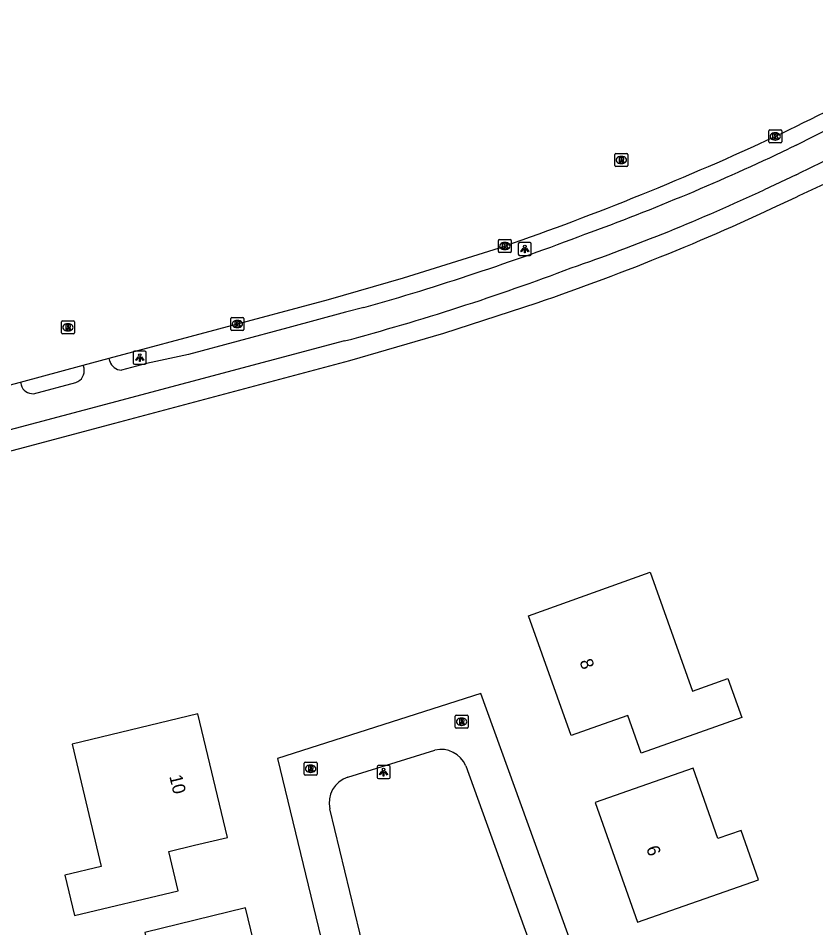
# Model space of a CAD drawing. Extents: x 162675 to 163482, y 379761 to 381227.
# Drawn here: x 162939.9 to 163001.5, y 380812.4 to 380882.6 of the extents above; entities that cross this region are included whole.
import ezdxf

# ---------------------------------------------------------------- set-up
doc = ezdxf.new("R2010")
doc.units = 0
for name, color, linetype in [('IMGEO_Fietspad_open', 7, 'Continuous'), ('IMGEO_Kolk', 7, 'Continuous'), ('IMGEO_Lichtpunt', 7, 'Continuous'), ('IMGEO_Pand', 7, 'Continuous'), ('IMGEO_Pand_nummerreeks', 7, 'Continuous'), ('IMGEO_Rijbaan_lokaal_gesloten', 7, 'Continuous'), ('IMGEO_Rioolput', 7, 'Continuous'), ('IMGEO_Voetpad_open', 7, 'Continuous')]:
    doc.layers.add(name, color=color, linetype=linetype)

msp = doc.modelspace()

# ---------------------------------------------------------------- linework, layer by layer
at = {"layer": 'IMGEO_Fietspad_open'}
for points in [[(163000.009, 380872.843), (162999.411, 380872.547)], [(163000, 380870.549), (162997.546, 380869.389)], [(162966.635, 380860.294), (162965.204, 380859.933), (162960.769, 380858.729), (162953.091, 380856.665), (162949.842, 380855.977), (162947.908, 380855.475)], [(162965.132, 380857.723), (162947.072, 380852.929), (162883.309, 380836.002), (162829.587, 380821.611), (162829.396, 380821.566)], [(162947.01, 380856.162), (162946.953, 380856.388)], [(162945.022, 380855.613), (162944.959, 380855.848)], [(162940.109, 380854.549), (162940.164, 380854.327)], [(162941.129, 380853.653), (162944.388, 380854.52)]]:
    msp.add_lwpolyline(points, dxfattribs=at)
for centre, radius, start, end in [((162863.234, 381148.559), 307.777, 296.38462, 299.42705), ((162902.998, 381072.888), 224.389, 295.61337, 299.67767), ((162922.893, 381032.807), 177.59, 290.02175, 295.5226), ((162931.903, 381010.136), 155.302, 289.07011, 295.00391), ((162907.827, 381066.245), 214.183, 285.93638, 290.74602), ((162917.882, 381034.623), 183.102, 284.95472, 290.71356), ((162944.091, 380855.423), 0.95, 288.22191, 11.54591), ((162947.929, 380856.434), 0.959, 196.45042, 268.71519), ((162941.062, 380854.585), 0.934, 196.0322, 274.10339)]:
    msp.add_arc(centre, radius, start, end, dxfattribs=at)
at = {"layer": 'IMGEO_Kolk'}
for p, q in [((162997.891, 380873.076), (162997.891, 380873.928)), ((162997.966, 380874.002), (162998.818, 380874.002)), ((162998.379, 380873.782), (162998.404, 380873.782)), ((162998.892, 380873.928), (162998.892, 380873.076)), ((162998.402, 380873.222), (162998.377, 380873.222)), ((162998.818, 380873.002), (162997.966, 380873.002)), ((162977.014, 380864.622), (162977.014, 380865.474)), ((162977.089, 380865.548), (162977.941, 380865.548)), ((162978.015, 380865.474), (162978.015, 380864.622)), ((162977.525, 380864.768), (162977.5, 380864.768)), ((162977.502, 380865.328), (162977.527, 380865.328)), ((162977.941, 380864.548), (162977.089, 380864.548)), ((162956.359, 380858.603), (162956.359, 380859.455)), ((162956.434, 380859.529), (162957.286, 380859.529)), ((162956.847, 380859.309), (162956.872, 380859.309)), ((162957.36, 380859.455), (162957.36, 380858.603)), ((162957.286, 380858.529), (162956.434, 380858.529)), ((162956.87, 380858.749), (162956.845, 380858.749))]:
    msp.add_line(p, q, dxfattribs=at)
for points in [[(162997.891, 380873.076), (162997.891, 380873.928)], [(162997.966, 380874.002), (162998.818, 380874.002)], [(162998.892, 380873.928), (162998.892, 380873.076)], [(162998.212, 380873.702), (162998.335, 380873.702), (162998.335, 380873.551), (162998.465, 380873.702), (162998.629, 380873.702), (162998.483, 380873.551), (162998.636, 380873.302), (162998.484, 380873.302), (162998.399, 380873.466), (162998.335, 380873.399), (162998.335, 380873.302), (162998.212, 380873.302), (162998.212, 380873.702)], [(162998.818, 380873.002), (162997.966, 380873.002)], [(162977.014, 380864.622), (162977.014, 380865.474)], [(162977.089, 380865.548), (162977.941, 380865.548)], [(162978.015, 380865.474), (162978.015, 380864.622)], [(162977.335, 380865.248), (162977.458, 380865.248), (162977.458, 380865.097), (162977.588, 380865.248), (162977.752, 380865.248), (162977.606, 380865.097), (162977.759, 380864.848), (162977.607, 380864.848), (162977.522, 380865.012), (162977.458, 380864.945), (162977.458, 380864.848), (162977.335, 380864.848), (162977.335, 380865.248)], [(162977.941, 380864.548), (162977.089, 380864.548)], [(162956.359, 380858.603), (162956.359, 380859.455)], [(162956.434, 380859.529), (162957.286, 380859.529)], [(162956.68, 380859.229), (162956.803, 380859.229), (162956.803, 380859.078), (162956.933, 380859.229), (162957.097, 380859.229), (162956.951, 380859.078), (162957.104, 380858.829), (162956.952, 380858.829), (162956.867, 380858.993), (162956.803, 380858.926), (162956.803, 380858.829), (162956.68, 380858.829), (162956.68, 380859.229)], [(162957.36, 380859.455), (162957.36, 380858.603)], [(162957.286, 380858.529), (162956.434, 380858.529)]]:
    msp.add_lwpolyline(points, dxfattribs=at)
for centre, start, end in [((162997.968, 380873.926), 91.55205, 178.44795), ((162997.968, 380873.926), 91.55205, 178.44795), ((162998.816, 380873.926), 1.55205, 88.44795), ((162998.816, 380873.926), 1.55205, 88.44795), ((162997.968, 380873.078), 181.55205, 268.44795), ((162997.968, 380873.078), 181.55205, 268.44795), ((162998.816, 380873.078), 271.55205, 358.44795), ((162998.816, 380873.078), 271.55205, 358.44795), ((162977.091, 380865.472), 91.55205, 178.44795), ((162977.091, 380865.472), 91.55205, 178.44795), ((162977.939, 380865.472), 1.55205, 88.44795), ((162977.939, 380865.472), 1.55205, 88.44795), ((162977.091, 380864.624), 181.55205, 268.44795), ((162977.091, 380864.624), 181.55205, 268.44795), ((162977.939, 380864.624), 271.55205, 358.44795), ((162977.939, 380864.624), 271.55205, 358.44795), ((162956.436, 380859.453), 91.55205, 178.44795), ((162956.436, 380859.453), 91.55205, 178.44795), ((162957.284, 380859.453), 1.55205, 88.44795), ((162957.284, 380859.453), 1.55205, 88.44795), ((162956.436, 380858.605), 181.55205, 268.44795), ((162956.436, 380858.605), 181.55205, 268.44795), ((162957.284, 380858.605), 271.55205, 358.44795), ((162957.284, 380858.605), 271.55205, 358.44795)]:
    msp.add_arc(centre, 0.0765, start, end, dxfattribs=at)
for centre, major_axis, ratio, start_param, end_param in [((162998.378, 380873.502), (-0.387, 0.002), 0.722429, 4.712389, 7.853982), ((162998.403, 380873.502), (-0.39, 0.002), 0.717154, 1.570796, 4.712389), ((162977.501, 380865.048), (-0.387, 0.002), 0.722429, 4.712389, 7.853982), ((162977.526, 380865.048), (-0.39, 0.002), 0.717154, 1.570796, 4.712389), ((162956.846, 380859.029), (-0.387, 0.002), 0.722429, 4.712389, 7.853982), ((162956.871, 380859.029), (-0.39, 0.002), 0.717154, 1.570796, 4.712389)]:
    msp.add_ellipse(centre, major_axis=major_axis, ratio=ratio, start_param=start_param, end_param=end_param, dxfattribs=at)
at = {"layer": 'IMGEO_Lichtpunt'}
for p, q in [((162978.556, 380865.216), (162978.556, 380864.409)), ((162978.556, 380865.216), (162978.556, 380864.409)), ((162979.458, 380865.311), (162978.65, 380865.311)), ((162979.458, 380865.311), (162978.65, 380865.311)), ((162979.552, 380864.409), (162979.552, 380865.216)), ((162979.552, 380864.409), (162979.552, 380865.216)), ((162978.65, 380864.315), (162979.458, 380864.315)), ((162978.65, 380864.315), (162979.458, 380864.315)), ((162949.724, 380856.929), (162948.916, 380856.929)), ((162949.724, 380856.929), (162948.916, 380856.929)), ((162948.822, 380856.834), (162948.822, 380856.027)), ((162948.822, 380856.834), (162948.822, 380856.027)), ((162949.818, 380856.027), (162949.818, 380856.834)), ((162949.818, 380856.027), (162949.818, 380856.834)), ((162948.916, 380855.933), (162949.724, 380855.933)), ((162948.916, 380855.933), (162949.724, 380855.933)), ((162967.654, 380824.852), (162967.654, 380824.045)), ((162967.654, 380824.852), (162967.654, 380824.045)), ((162968.556, 380824.947), (162967.748, 380824.947)), ((162968.556, 380824.947), (162967.748, 380824.947)), ((162968.65, 380824.045), (162968.65, 380824.852)), ((162968.65, 380824.045), (162968.65, 380824.852)), ((162967.748, 380823.951), (162968.556, 380823.951)), ((162967.748, 380823.951), (162968.556, 380823.951))]:
    msp.add_line(p, q, dxfattribs=at)
for points in [[(162978.93, 380864.88), (162978.969, 380864.852), (162978.781, 380864.59), (162978.743, 380864.617), (162978.93, 380864.88)], [(162979.032, 380864.832), (162979.079, 380864.832), (162979.079, 380864.51), (162979.032, 380864.51), (162979.032, 380864.832)], [(162979.142, 380864.852), (162979.18, 380864.879), (162979.367, 380864.617), (162979.328, 380864.589), (162979.142, 380864.852)], [(162949.196, 380856.498), (162949.235, 380856.47), (162949.047, 380856.208), (162949.009, 380856.235), (162949.196, 380856.498)], [(162949.298, 380856.45), (162949.345, 380856.45), (162949.345, 380856.128), (162949.298, 380856.128), (162949.298, 380856.45)], [(162949.408, 380856.47), (162949.446, 380856.497), (162949.633, 380856.235), (162949.594, 380856.207), (162949.408, 380856.47)], [(162968.028, 380824.516), (162968.067, 380824.488), (162967.879, 380824.226), (162967.841, 380824.253), (162968.028, 380824.516)], [(162968.13, 380824.468), (162968.177, 380824.468), (162968.177, 380824.146), (162968.13, 380824.146), (162968.13, 380824.468)], [(162968.24, 380824.488), (162968.278, 380824.515), (162968.465, 380824.253), (162968.426, 380824.225), (162968.24, 380824.488)]]:
    msp.add_lwpolyline(points, dxfattribs=at)
for centre in [(162979.055, 380865.014), (162949.321, 380856.632), (162968.153, 380824.65)]:
    msp.add_circle(centre, 0.0994, dxfattribs=at)
for centre, start, end in [((162978.65, 380865.216), 90, 180), ((162978.65, 380865.216), 90, 180), ((162979.458, 380865.216), 0, 90), ((162979.458, 380865.216), 0, 90), ((162978.65, 380864.409), 180, 270), ((162978.65, 380864.409), 180, 270), ((162979.458, 380864.409), 270, 0), ((162979.458, 380864.409), 270, 360), ((162948.916, 380856.834), 90, 180), ((162948.916, 380856.834), 90, 180), ((162949.724, 380856.834), 0, 90), ((162949.724, 380856.834), 0, 90), ((162948.916, 380856.027), 180, 270), ((162948.916, 380856.027), 180, 270), ((162949.724, 380856.027), 270, 0), ((162949.724, 380856.027), 270, 360), ((162967.748, 380824.852), 90, 180), ((162967.748, 380824.852), 90, 180), ((162968.556, 380824.852), 0, 90), ((162968.556, 380824.852), 0, 90), ((162967.748, 380824.045), 180, 270), ((162967.748, 380824.045), 180, 270), ((162968.556, 380824.045), 270, 0), ((162968.556, 380824.045), 270, 360)]:
    msp.add_arc(centre, 0.0946, start, end, dxfattribs=at)
at = {"layer": 'IMGEO_Pand'}
for points in [[(162982.628, 380827.263), (162979.336, 380836.52), (162988.748, 380839.868), (162992.007, 380830.705), (162994.739, 380831.677), (162995.812, 380828.662), (162988.048, 380825.9), (162987.009, 380828.821), (162985.106, 380828.144), (162982.628, 380827.263)], [(162953.545, 380818.799), (162956.101, 380819.412), (162953.816, 380828.945), (162944.092, 380826.615), (162946.356, 380817.167), (162943.539, 380816.492), (162944.287, 380813.373), (162952.298, 380815.293), (162951.571, 380818.326), (162953.545, 380818.799)], [(162987.748, 380812.863), (162997.089, 380816.143), (162995.754, 380819.945), (162993.961, 380819.316), (162992.049, 380824.761), (162984.501, 380822.11), (162987.748, 380812.863)], [(162957.493, 380813.963), (162949.719, 380812.074), (162951.081, 380806.467), (162949.235, 380806.018), (162948.406, 380805.816), (162949.357, 380801.901), (162950.186, 380802.102), (162959.806, 380804.439), (162957.493, 380813.963)]]:
    msp.add_lwpolyline(points, dxfattribs=at)
at = {"layer": 'IMGEO_Rijbaan_lokaal_gesloten'}
for points in [[(162946.953, 380856.388), (162963.908, 380860.926), (162969.679, 380862.589), (162977.515, 380865.048)], [(162944.959, 380855.848), (162946.953, 380856.388)], [(162940.109, 380854.549), (162944.959, 380855.848)], [(162938.044, 380853.996), (162940.109, 380854.549)]]:
    msp.add_lwpolyline(points, dxfattribs=at)
for centre, radius, start, end in [((162891.807, 381095.555), 246.308, 295.64099, 300.17799), ((162902.212, 381081.012), 228.716, 289.22279, 294.86751)]:
    msp.add_arc(centre, radius, start, end, dxfattribs=at)
at = {"layer": 'IMGEO_Rioolput'}
for p, q in [((162986.008, 380871.257), (162986.008, 380872.109)), ((162986.083, 380872.183), (162986.935, 380872.183)), ((162986.496, 380871.963), (162986.521, 380871.963)), ((162987.009, 380872.109), (162987.009, 380871.257)), ((162986.935, 380871.183), (162986.083, 380871.183)), ((162986.519, 380871.403), (162986.494, 380871.403)), ((162943.278, 380858.344), (162943.278, 380859.196)), ((162943.353, 380859.27), (162944.205, 380859.27)), ((162943.766, 380859.05), (162943.791, 380859.05)), ((162944.279, 380859.196), (162944.279, 380858.344)), ((162943.789, 380858.49), (162943.764, 380858.49)), ((162944.205, 380858.27), (162943.353, 380858.27)), ((162973.677, 380827.911), (162973.677, 380828.763)), ((162973.752, 380828.837), (162974.604, 380828.837)), ((162974.165, 380828.617), (162974.19, 380828.617)), ((162974.678, 380828.763), (162974.678, 380827.911)), ((162974.604, 380827.837), (162973.752, 380827.837)), ((162974.188, 380828.057), (162974.163, 380828.057)), ((162962.019, 380824.278), (162962.019, 380825.13)), ((162962.094, 380825.204), (162962.946, 380825.204)), ((162962.507, 380824.984), (162962.532, 380824.984)), ((162963.02, 380825.13), (162963.02, 380824.278)), ((162962.946, 380824.204), (162962.094, 380824.204)), ((162962.53, 380824.424), (162962.505, 380824.424))]:
    msp.add_line(p, q, dxfattribs=at)
for points in [[(162986.008, 380871.257), (162986.008, 380872.109)], [(162986.083, 380872.183), (162986.935, 380872.183)], [(162986.597, 380871.881), (162986.345, 380871.883), (162986.345, 380871.483)], [(162986.523, 380871.802), (162986.469, 380871.802), (162986.469, 380871.721)], [(162986.469, 380871.721), (162986.521, 380871.721)], [(162987.009, 380872.109), (162987.009, 380871.257)], [(162986.935, 380871.183), (162986.083, 380871.183)], [(162986.345, 380871.483), (162986.469, 380871.483), (162986.469, 380871.645), (162986.48, 380871.645)], [(162986.527, 380871.616), (162986.598, 380871.483), (162986.738, 380871.483), (162986.673, 380871.609)], [(162943.278, 380858.344), (162943.278, 380859.196)], [(162943.353, 380859.27), (162944.205, 380859.27)], [(162944.279, 380859.196), (162944.279, 380858.344)], [(162943.867, 380858.968), (162943.615, 380858.97), (162943.615, 380858.57)], [(162943.615, 380858.57), (162943.739, 380858.57), (162943.739, 380858.732), (162943.75, 380858.732)], [(162943.793, 380858.889), (162943.739, 380858.889), (162943.739, 380858.808)], [(162943.739, 380858.808), (162943.791, 380858.808)], [(162943.797, 380858.703), (162943.868, 380858.57), (162944.008, 380858.57), (162943.943, 380858.696)], [(162944.205, 380858.27), (162943.353, 380858.27)], [(162973.677, 380827.911), (162973.677, 380828.763)], [(162973.752, 380828.837), (162974.604, 380828.837)], [(162974.266, 380828.535), (162974.014, 380828.537), (162974.014, 380828.137)], [(162974.014, 380828.137), (162974.138, 380828.137), (162974.138, 380828.299), (162974.149, 380828.299)], [(162974.192, 380828.456), (162974.138, 380828.456), (162974.138, 380828.375)], [(162974.138, 380828.375), (162974.19, 380828.375)], [(162974.196, 380828.27), (162974.267, 380828.137), (162974.407, 380828.137), (162974.342, 380828.263)], [(162974.678, 380828.763), (162974.678, 380827.911)], [(162974.604, 380827.837), (162973.752, 380827.837)], [(162962.019, 380824.278), (162962.019, 380825.13)], [(162962.094, 380825.204), (162962.946, 380825.204)], [(162962.608, 380824.902), (162962.356, 380824.904), (162962.356, 380824.504)], [(162962.356, 380824.504), (162962.48, 380824.504), (162962.48, 380824.666), (162962.491, 380824.666)], [(162962.534, 380824.823), (162962.48, 380824.823), (162962.48, 380824.742)], [(162962.48, 380824.742), (162962.532, 380824.742)], [(162962.538, 380824.637), (162962.609, 380824.504), (162962.749, 380824.504), (162962.684, 380824.63)], [(162963.02, 380825.13), (162963.02, 380824.278)], [(162962.946, 380824.204), (162962.094, 380824.204)]]:
    msp.add_lwpolyline(points, dxfattribs=at)
for centre, radius, start, end in [((162986.085, 380872.107), 0.0765, 91.55205, 178.44795), ((162986.085, 380872.107), 0.0765, 91.55205, 178.44795), ((162986.505, 380871.91), 0.19, 274.7715, 282.96867), ((162986.529, 380871.706), 0.0964, 77.00612, 93.18647), ((162986.543, 380871.763), 0.0378, 276.66336, 79.67722), ((162986.596, 380871.771), 0.109, 350.36119, 89.41601), ((162986.594, 380871.771), 0.112, 277.58423, 350.98172), ((162986.578, 380871.556), 0.108, 29.51342, 73.79051), ((162986.933, 380872.107), 0.0765, 1.55205, 88.44795), ((162986.933, 380872.107), 0.0765, 1.55205, 88.44795), ((162986.085, 380871.259), 0.0765, 181.55205, 268.44795), ((162986.085, 380871.259), 0.0765, 181.55205, 268.44795), ((162986.479, 380871.592), 0.0533, 26.02933, 88.69889), ((162986.933, 380871.259), 0.0765, 271.55205, 358.44795), ((162986.933, 380871.259), 0.0765, 271.55205, 358.44795), ((162943.355, 380859.194), 0.0765, 91.55205, 178.44795), ((162943.355, 380859.194), 0.0765, 91.55205, 178.44795), ((162944.203, 380859.194), 0.0765, 1.55205, 88.44795), ((162944.203, 380859.194), 0.0765, 1.55205, 88.44795), ((162943.355, 380858.346), 0.0765, 181.55205, 268.44795), ((162943.355, 380858.346), 0.0765, 181.55205, 268.44795), ((162943.749, 380858.679), 0.0533, 26.02933, 88.69889), ((162943.775, 380858.997), 0.19, 274.7715, 282.96867), ((162943.799, 380858.793), 0.0964, 77.00612, 93.18647), ((162943.813, 380858.85), 0.0378, 276.66336, 79.67722), ((162943.866, 380858.858), 0.109, 350.36119, 89.41601), ((162943.864, 380858.858), 0.112, 277.58423, 350.98172), ((162943.848, 380858.643), 0.108, 29.51342, 73.79051), ((162944.203, 380858.346), 0.0765, 271.55205, 358.44795), ((162944.203, 380858.346), 0.0765, 271.55205, 358.44795), ((162973.754, 380828.761), 0.0765, 91.55205, 178.44795), ((162973.754, 380828.761), 0.0765, 91.55205, 178.44795), ((162974.148, 380828.246), 0.0533, 26.02933, 88.69889), ((162974.174, 380828.564), 0.19, 274.7715, 282.96867), ((162974.198, 380828.36), 0.0964, 77.00612, 93.18647), ((162974.212, 380828.417), 0.0378, 276.66336, 79.67722), ((162974.265, 380828.425), 0.109, 350.36119, 89.41601), ((162974.263, 380828.425), 0.112, 277.58423, 350.98172), ((162974.247, 380828.21), 0.108, 29.51342, 73.79051), ((162974.602, 380828.761), 0.0765, 1.55205, 88.44795), ((162974.602, 380828.761), 0.0765, 1.55205, 88.44795), ((162973.754, 380827.913), 0.0765, 181.55205, 268.44795), ((162973.754, 380827.913), 0.0765, 181.55205, 268.44795), ((162974.602, 380827.913), 0.0765, 271.55205, 358.44795), ((162974.602, 380827.913), 0.0765, 271.55205, 358.44795), ((162962.096, 380825.128), 0.0765, 91.55205, 178.44795), ((162962.096, 380825.128), 0.0765, 91.55205, 178.44795), ((162962.49, 380824.613), 0.0533, 26.02933, 88.69889), ((162962.516, 380824.931), 0.19, 274.7715, 282.96867), ((162962.54, 380824.727), 0.0964, 77.00612, 93.18647), ((162962.554, 380824.784), 0.0378, 276.66336, 79.67722), ((162962.607, 380824.792), 0.109, 350.36119, 89.41601), ((162962.605, 380824.792), 0.112, 277.58423, 350.98172), ((162962.589, 380824.577), 0.108, 29.51342, 73.79051), ((162962.944, 380825.128), 0.0765, 1.55205, 88.44795), ((162962.944, 380825.128), 0.0765, 1.55205, 88.44795), ((162962.096, 380824.28), 0.0765, 181.55205, 268.44795), ((162962.096, 380824.28), 0.0765, 181.55205, 268.44795), ((162962.944, 380824.28), 0.0765, 271.55205, 358.44795), ((162962.944, 380824.28), 0.0765, 271.55205, 358.44795)]:
    msp.add_arc(centre, radius, start, end, dxfattribs=at)
for centre, major_axis, ratio, start_param, end_param in [((162986.495, 380871.683), (-0.387, 0.002), 0.722429, 4.712389, 7.853982), ((162986.52, 380871.683), (-0.39, 0.002), 0.717154, 1.570796, 4.712389), ((162943.765, 380858.77), (-0.387, 0.002), 0.722429, 4.712389, 7.853982), ((162943.79, 380858.77), (-0.39, 0.002), 0.717154, 1.570796, 4.712389), ((162974.164, 380828.337), (-0.387, 0.002), 0.722429, 4.712389, 7.853982), ((162974.189, 380828.337), (-0.39, 0.002), 0.717154, 1.570796, 4.712389), ((162962.506, 380824.704), (-0.387, 0.002), 0.722429, 4.712389, 7.853982), ((162962.531, 380824.704), (-0.39, 0.002), 0.717154, 1.570796, 4.712389)]:
    msp.add_ellipse(centre, major_axis=major_axis, ratio=ratio, start_param=start_param, end_param=end_param, dxfattribs=at)
at = {"layer": 'IMGEO_Voetpad_open'}
for points in [[(163000, 380868.822), (163000.253, 380868.942)], [(162829.461, 380819.913), (162829.67, 380819.973), (162881.58, 380833.855), (162947.405, 380851.384), (162965.533, 380856.211), (162972.81, 380858.32), (162980.011, 380860.673)], [(162992.18, 380784.912), (162983.99, 380807.505), (162975.656, 380830.504), (162959.948, 380825.491), (162965.296, 380803.494), (162971.296, 380778.555)], [(162965.394, 380824.046), (162972.116, 380826.134)], [(162974.496, 380824.924), (162980.643, 380807.906), (162989.357, 380783.869), (162989.418, 380783.701)], [(162974.235, 380779.267), (162968.622, 380802.474), (162964.008, 380821.602)]]:
    msp.add_lwpolyline(points, dxfattribs=at)
for centre, radius, start, end in [((162910.329, 381062.754), 213.657, 294.89008, 301.20708), ((162920.679, 381034.802), 183.96, 288.81592, 295.54299), ((162972.608, 380824.157), 2.038, 22.11986, 103.98227), ((162966.002, 380822.086), 2.052, 107.24465, 193.63994)]:
    msp.add_arc(centre, radius, start, end, dxfattribs=at)

# ---------------------------------------------------------------- texts
at = {"layer": 'IMGEO_Pand_nummerreeks'}
for s, rotation, p in [('8', 289.57864, (162983.266, 380832.989)), ('10', 283.47551, (162951.598, 380824.126)), ('6', 289.34826, (162988.412, 380818.581))]:
    msp.add_text(s, height=1, rotation=rotation, dxfattribs=at).set_placement(p)

doc.saveas('drawing.dxf')
